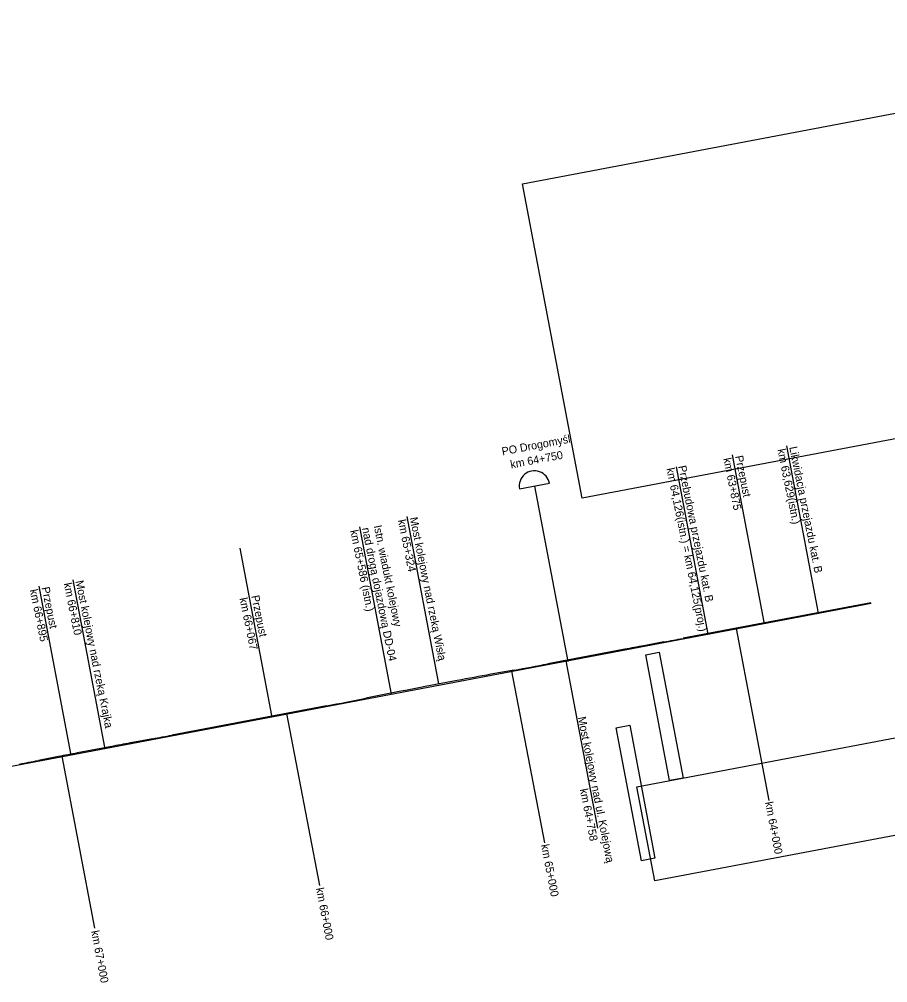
# Model space of a CAD drawing. Extents: x 6540591 to 6566579, y 5525343 to 5532423.
# Drawn here: x 6552007 to 6555803, y 5526691 to 5530905 of the extents above; entities that cross this region are included whole.
import ezdxf

# ---------------------------------------------------------------- set-up
doc = ezdxf.new("R2010")
doc.units = 0
for name, color, linetype in [('TOR_PS_OPIS_T-hektometry projektowane', 7, 'Continuous'), ('TOR_PS_OPIS_T-opisy dodatkowe', 7, 'Continuous'), ('TOR_PS_T-tory projektowane', 7, 'Continuous')]:
    doc.layers.add(name, color=color, linetype=linetype)

msp = doc.modelspace()

# ---------------------------------------------------------------- linework, layer by layer
at = {"layer": 'DEFPOINTS'}
for points in [[(6558266.4, 5529530.7), (6554467.2, 5528810.1), (6554206.5, 5530184.8), (6558005.7, 5530905.3)], [(6554909.3, 5527586), (6554849.8, 5527574.7), (6554745.4, 5528125.4), (6554804.9, 5528136.6)], [(6554785.7, 5527235.3), (6554726.3, 5527224), (6554616, 5527805.4), (6554675.5, 5527816.7)], [(6556259.2, 5527415.6), (6554784.7, 5527135.9), (6554706.7, 5527547.6), (6556181.1, 5527827.2)]]:
    msp.add_lwpolyline(points, close=True, dxfattribs=at)
at = {"layer": 'TOR_PS_OPIS_T-hektometry projektowane'}
for points in [[(6555140.5, 5528240.1), (6555283, 5527488.5)], [(6554158.1, 5528053.3), (6554303.6, 5527302.2)], [(6553175.2, 5527868.9), (6553318.7, 5527115.6)], [(6552192.9, 5527681.6), (6552335.2, 5526929.3)]]:
    msp.add_lwpolyline(points, dxfattribs=at)
at = {"layer": 'TOR_PS_OPIS_T-opisy dodatkowe'}
for p, q in [((6555360.6, 5529039), (6555499.3, 5528307)), ((6555123.8, 5528999.4), (6555262.5, 5528267.5)), ((6554878.1, 5528947.5), (6555016.9, 5528215.6)), ((6554193.5, 5528850.9), (6554324.5, 5528875.7)), ((6553701.1, 5528729.7), (6553839.9, 5527997.8)), ((6553493.5, 5528685.1), (6553632.3, 5527953.1)), ((6552970.2, 5528591.2), (6553108.9, 5527859.2)), ((6552240.3, 5528452.8), (6552379, 5527720.9)), ((6552092, 5528424.7), (6552230.7, 5527692.8)), ((6554395.9, 5528098.1), (6554534.7, 5527366.1))]:
    msp.add_line(p, q, dxfattribs=at)
msp.add_lwpolyline([(6554259, 5528863.3), (6554404.5, 5528095.6)], dxfattribs=at)
msp.add_arc((6554259, 5528863.3), 66.7, 10.7332, 190.7332, dxfattribs=at)
at = {"layer": 'TOR_PS_T-tory projektowane'}
for p, q in [((6555729.8, 5528352.9), (6554908.5, 5528197.2)), ((6555730.5, 5528348.9), (6550837.1, 5527421.3)), ((6554825, 5528181.5), (6554737, 5528165)), ((6554653.5, 5528149.3), (6554317.3, 5528085.6)), ((6554169.8, 5528058.3), (6554068.7, 5528039.9)), ((6553921.2, 5528012.6), (6553781.6, 5527986.1)), ((6553609.8, 5527952.7), (6553522.3, 5527935.3)), ((6553350.5, 5527901.9), (6552673.7, 5527773.6)), ((6552418.7, 5527725.7), (6552261.5, 5527695.9)), ((6552590.1, 5527757.9), (6552502.2, 5527741.4)), ((6552178, 5527680), (6552090.2, 5527663.1)), ((6552178, 5527680), (6552090.2, 5527663.1))]:
    msp.add_line(p, q, dxfattribs=at)
for centre, radius, start, end in [((6548772, 5560570.7), 32950, 280.58543, 280.73324), ((6560790, 5495775.8), 32950, 100.58543, 100.73324), ((6550871.9, 5546261.9), 18500, 280.26868, 280.73324), ((6557366.5, 5509836.2), 18500, 100.26868, 100.73324), ((6557227, 5509809.8), 18500, 100.73324, 101.27525), ((6549905.1, 5546078.2), 18500, 280.73324, 281.27525), ((6546537.2, 5560147.1), 32950, 280.58543, 280.73324), ((6558555.2, 5495352.2), 32950, 100.58543, 100.73324), ((6558398, 5495322.4), 32950, 100.73324, 100.88104), ((6545870.2, 5560020.7), 32950, 280.73324, 280.88104)]:
    msp.add_arc(centre, radius, start, end, dxfattribs=at)

# ---------------------------------------------------------------- texts
at = {"layer": 'TOR_PS_OPIS_T-hektometry projektowane'}
for s, rotation, p in [('km 64+000', 280.7332, (6555266.9, 5527479.5)), ('km 65+000', 280.9655, (6554287.5, 5527293.2)), ('km 66+000', 280.7814, (6553303.7, 5527103.4)), ('km 67+000', 280.7075, (6552320.4, 5526916))]:
    msp.add_text(s, height=35, rotation=rotation, dxfattribs=at).set_placement(p)
at = {"layer": 'TOR_PS_OPIS_T-opisy dodatkowe'}
for s, rotation, p in [('PO Drogomyśl', 10.7332, (6554119.4, 5528997.2)), ('km 63,629(istn.)', 281.4331, (6555321.2, 5529022.8)), ('Likwidacja przejazdu kat. B', 281.4331, (6555372.7, 5529033.2)), ('km 64+750', 10.7332, (6554157, 5528940.2)), ('km 63+875', 281.4331, (6555084.4, 5528983.2)), ('Przepust', 281.4331, (6555135.9, 5528993.6)), ('km 64,126(istn.) = km 64,125(proj.)', 281.4331, (6554835.9, 5528939.5)), ('Przebudowa przejazdu kat. B', 281.4331, (6554887.3, 5528949.9)), ('Istn. wiadukt kolejowy ', 281.4331, (6553556.2, 5528688.9)), ('km 65+324', 281.4331, (6553661.8, 5528713.6)), ('Most kolejowy nad rzeką Wisłą', 281.4331, (6553713.2, 5528724)), ('km 65+586 (istn.)', 281.4331, (6553453.3, 5528668.1)), ('nad drogą dojazdową DD-04', 281.4331, (6553504.7, 5528678.5)), ('km 66+810', 281.4331, (6552200.9, 5528436.7)), ('Most kolejowy nad rzeką Krajka', 281.4331, (6552252.4, 5528447.1)), ('km 66+895', 281.4331, (6552052.6, 5528408.5)), ('Przepust', 281.4331, (6552104.1, 5528418.9)), ('km 66+067', 281.4331, (6552969.4, 5528371.8)), ('Przepust', 281.4331, (6553020.8, 5528382.2)), ('Most kolejowy nad ul. Kolejową', 281.1578, (6554448.5, 5527851.2)), ('km 64+758', 281.1578, (6554457.1, 5527536.3))]:
    msp.add_text(s, height=35, rotation=rotation, dxfattribs=at).set_placement(p)

doc.saveas('drawing.dxf')
